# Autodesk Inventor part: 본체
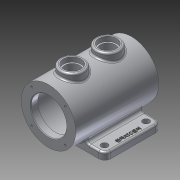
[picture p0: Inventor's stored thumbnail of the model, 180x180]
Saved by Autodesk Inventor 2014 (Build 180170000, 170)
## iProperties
Created: 2014-12
Part Number: 본체
Material: 알루미늄 6061
Document SubType Name: Modeling
Designer: Owner
Density: 2.71 g/cm^3
Appearance: 알루미늄 - 평지
Mass: 1300.09 g
Surface Area: 1035.66 cm^2
Volume: 479.737 cm^3
Author: Owner
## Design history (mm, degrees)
sketch "스케치1"
  geometry: C1 r 46 at (0, 0); 1 further point
  constraints: 1 centre point, 1 coincident
  dimensions: "d0" = 92 diameter of C1
extrude "돌출1" new body sketch "스케치1" stored distance "d1" = 140; taper "d2" = 0 deg
sketch "스케치2"
  geometry: C1 r 46 at (0, 0) reference; C2 r 30 at (0, 0)
  constraints: 1 centre point, 1 coincident
  dimensions: "d3" = 60 diameter of C2
extrude "돌출2" cut sketch "스케치2" distance "d4" = 12; taper "d5" = 0 deg
sketch "스케치3"
  geometry: C1 r 46 at (0, 0) reference; C2 r 30 at (0, 0)
  constraints: 1 centre point, 1 coincident
  dimensions: "d6" = 60 diameter of C2
extrude "돌출3" cut sketch "스케치3" distance "d7" = 12; taper "d8" = 0 deg
sketch "스케치4"
  geometry: C1 r 30 at (0, 0) reference; C2 r 37.5 at (0, 0)
  constraints: 1 centre point, 1 coincident
  dimensions: "d9" = 75 diameter of C2
extrude "돌출4" cut sketch "스케치4" distance "d10" = 116; taper "d11" = 0 deg
node "작업 평면2"
sketch "스케치7"
  geometry: L1 (-46, -70)-(46, -70) reference; C1 r 20 at (0, -30); C2 r 20 at (0, 30); 1 further point
  constraints: 2 centre point, 2 vertical alignment
  dimensions: "d20" = 40 distance from line of C1.centre L1; "d21" = 60 distance of C2.centre C1.centre; "d22" = 40 diameter of C2; "d23" = 40 diameter of C1
extrude "돌출6" join sketch "스케치7" stored distance "d24" = 80; taper "d25" = 0 deg
sketch "스케치8"
  geometry: C1 r 20 at (0, 0) reference; C2 r 15 at (0, 0); 1 further point
  constraints: 1 centre point, 1 coincident
  dimensions: "d26" = 30 diameter of C2
extrude "돌출7" cut sketch "스케치8" distance "d27" = 8; taper "d28" = 0 deg
sketch "스케치9"
  geometry: C1 r 15 at (0, 0) reference; C2 r 12.5 at (0, 0); 1 further point
  constraints: 1 centre point, 1 coincident
  dimensions: "d29" = 25 diameter of C2
extrude "돌출8" cut sketch "스케치9" stored distance "d30" = 8; taper "d31" = 0 deg
node "작업 평면3"
sketch "스케치10"
  geometry: L1 (-65, 55)-(65, 55); L2 (65, 55)-(65, -40); L3 (65, -40)-(-65, -40); L4 (-65, -40)-(-65, 55); L5 (46, 70)-(-46, 70) reference; 3 further points
  constraints: 8 end point, 2 midpoint, 2 parallel, 1 horizontal, 1 perpendicular, 1 vertical alignment
  dimensions: "d33" = 15 distance between parallel lines of L5 L1; "d34" = 95 distance of L3.end L1.start; "d35" = 130 distance of L1.start L1.end
extrude "돌출9" join sketch "스케치10" distance "d36" = 12; taper "d37" = 0 deg
sketch "스케치11"
  geometry: L1 (65, -40)-(65, 55) reference; L2 (65, 55)-(25.923, 55) reference; C1 r 5.5 at (52, 42.5); 1 further point
  constraints: 1 centre point
  dimensions: "d38" = 12.5 distance from line of C1.centre L2; "d39" = 13 distance from line of L1 C1.centre; "d45" = 11 diameter of C1
extrude "돌출10" cut sketch "스케치11" stored distance "d40" = 12; taper "d41" = 0 deg
fillet "모깎기1" dims "d46" = 10
chamfer "모따기1" distance "d47" = 1; stored, may be unused: second distance "d48" = 2, angle "d49" = 45 deg
fillet "모깎기2" dims "d61" = 3
fillet "모깎기5" dims "d64" = 3
fillet "모깎기6" dims "d65" = 3
sketch "스케치13"
  geometry: L1 (65, -30)-(65, 45) reference; C1 r 5.5 at (52, -27.5) reference; 2 further points
  constraints: 1 other
  dimensions: "d66" = 8 distance from line of L1 point (57, 7.5); "d67" = 35 vertical distance of C1.centre point (57, 7.5)
feature "엠보싱1" sketch "스케치13" dims "d68" = 1, "d69" = 0
sketch "스케치14"
  geometry: L1 (0, 0)-(28.284, 28.284); L2 (0, 0)-(40, 0); C1 r 31 at (0, 0) reference; 1 further point
  constraints: 4 end point, 1 coincident, 1 equal length, 1 horizontal
  dimensions: "d74" = 40 distance of L1.start L1.end; "d75" = 45 deg angle of L2 L1
hole "구멍2" sketch "스케치14" at (28.284, 28.284) diameter "d76" = 3.242; stored, may be unused: countersink angle "d80" = 90 deg, drill point angle "d82" = 118 deg; dims "d77" = 9, "d78" = 4, "d79" = 2, "d81" = 10
fillet "모깎기8" dims "d86" = 5
fillet "모깎기9" dims "d87" = 3
fillet "모깎기10" dims "d88" = 3
node "솔리드1"
mirror "대칭1"
mirror "대칭4"
pattern_circular "원형 패턴2" dims angle "d84" = 360 deg
mirror "대칭5"
pattern_linear "직사각형 패턴3" dims "d91" = 70
pattern_linear "직사각형 패턴4" dims "d94" = 104
other parameters: "d19" = 56
